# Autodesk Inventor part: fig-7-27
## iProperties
Shininess: 77.0
Length Units: 11269
Angle Units: 11279
Time Units: 11290
Mass Units: 11283
Length Display Precision: 3
Angle Display Precision: 2
Created: 2002-01
Part Number: fig-7-27
Document SubType Name: Modeling
Designer: CADSoft
Density: 0.0
Volumn: 0.0
Area: 0.0
PropertySet Name: Model Information
Control State: 0
Master: False
Checked Out: False
Author: CADSoft
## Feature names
1. Coil5
